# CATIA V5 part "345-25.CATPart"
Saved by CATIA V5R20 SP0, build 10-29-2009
Part number: 345-25
Definition: NONE
Nomenclature: 345-25
Source: Unknown
Description: 345-25
Bounding box of the stored display mesh (mm): x 0 to 63, y -31.5 to 31.5, z -31.5 to 31.5
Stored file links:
  C:\Users\Utente\Desktop\IO LAVORO\3D X SITO CF\X SITO\345-346\345-25.CATPart
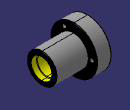
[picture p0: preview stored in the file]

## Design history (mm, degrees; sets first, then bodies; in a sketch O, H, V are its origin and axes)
Body1 "345-25" (main body)
  Solid1: solid without history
